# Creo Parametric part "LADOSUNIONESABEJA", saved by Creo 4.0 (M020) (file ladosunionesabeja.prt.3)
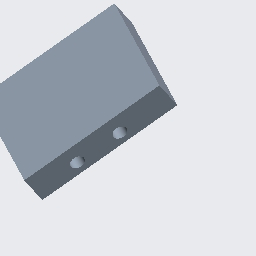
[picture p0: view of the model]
Units: millimeter Newton Second (mmNs); MM, TONNE, SECS

Created from: MMNS_PART_SOLID.PRT

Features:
  1. datum plane "RIGHT"
  2. datum plane "TOP"
  3. datum plane "FRONT"
  4. coordinate system
  5. sketch "Sketch 1"
  6. extrusion "Extrude 1"
  7. pattern "Pattern 1"
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
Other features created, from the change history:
  hole "Hole 1"
  hole "Hole 1 [2]"
  hole "Hole 1 [3]"
  hole "Hole 2"
  pattern "Patrón 2"
  hole "Taladro 2 [2]"

Surfaces: 11 plane, 5 cylinder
